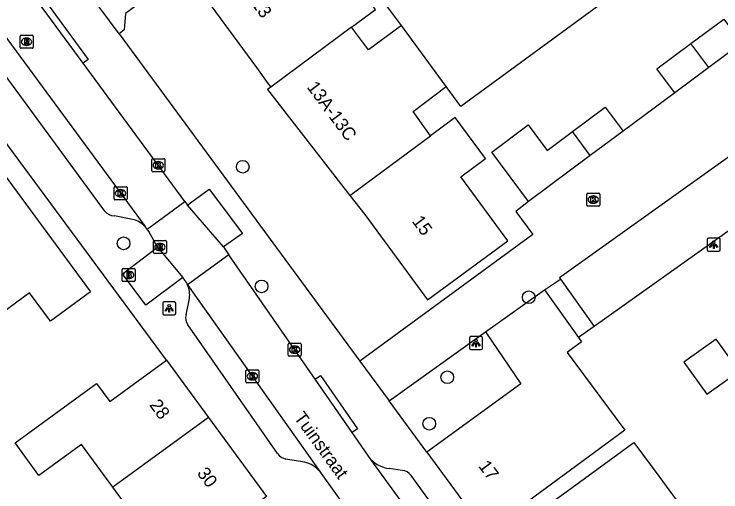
# Model space of a CAD drawing. Extents: x 161801 to 162379, y 382315 to 382832.
# Drawn here: x 161986.3 to 162040.7, y 382409.3 to 382446.1 of the extents above; entities that cross this region are included whole.
import ezdxf

# ---------------------------------------------------------------- set-up
doc = ezdxf.new("R2010")
doc.units = 0
for name, color, linetype in [('IMGEO_Boom', 7, 'Continuous'), ('IMGEO_Brandkraan', 7, 'Continuous'), ('IMGEO_Groenvoorziening', 7, 'Continuous'), ('IMGEO_Kolk', 7, 'Continuous'), ('IMGEO_Lichtpunt', 7, 'Continuous'), ('IMGEO_Openbare_ruimte_label', 7, 'Continuous'), ('IMGEO_Pand', 7, 'Continuous'), ('IMGEO_Pand_nummerreeks', 7, 'Continuous'), ('IMGEO_Parkeervlak_open', 7, 'Continuous'), ('IMGEO_Rijbaan_lokaal_open', 7, 'Continuous'), ('IMGEO_Rioolput', 7, 'Continuous'), ('IMGEO_Voetpad_open', 7, 'Continuous')]:
    doc.layers.add(name, color=color, linetype=linetype)

msp = doc.modelspace()

# ---------------------------------------------------------------- linework, layer by layer
at = {"layer": 'IMGEO_Boom'}
for centre in [(162003.926, 382434.351), (161994.753, 382428.459), (162005.374, 382425.139), (162025.931, 382424.312), (162019.656, 382418.146), (162018.277, 382414.57)]:
    msp.add_circle(centre, 0.489, dxfattribs=at)
at = {"layer": 'IMGEO_Brandkraan'}
for p, q in [((161994.641, 382425.6), (161994.641, 382426.452)), ((161994.716, 382426.526), (161995.568, 382426.526)), ((161995.129, 382426.306), (161995.154, 382426.306)), ((161995.642, 382426.452), (161995.642, 382425.6)), ((161995.152, 382425.746), (161995.127, 382425.746)), ((161995.568, 382425.526), (161994.716, 382425.526))]:
    msp.add_line(p, q, dxfattribs=at)
for points in [[(161994.641, 382425.6), (161994.641, 382426.452)], [(161994.716, 382426.526), (161995.568, 382426.526)], [(161994.989, 382426.226), (161994.989, 382425.826), (161995.202, 382425.826)], [(161995.22, 382426.226), (161994.989, 382426.226)], [(161995.168, 382426.145), (161995.114, 382426.145), (161995.114, 382426.069)], [(161995.642, 382426.452), (161995.642, 382425.6)], [(161995.114, 382426.069), (161995.167, 382426.069)], [(161995.176, 382425.993), (161995.114, 382425.993), (161995.114, 382425.912)], [(161995.114, 382425.912), (161995.176, 382425.912)], [(161995.568, 382425.526), (161994.716, 382425.526)]]:
    msp.add_lwpolyline(points, dxfattribs=at)
for centre, radius, start, end in [((161994.718, 382426.45), 0.0765, 91.552, 178.448), ((161994.718, 382426.45), 0.0765, 91.552, 178.448), ((161995.169, 382426.107), 0.0379, 267.8285, 90.9355), ((161995.224, 382426.081), 0.145, 59.4692, 91.5367), ((161995.249, 382426.128), 0.0922, 285.5137, 58.1501), ((161995.566, 382426.45), 0.0765, 1.552, 88.448), ((161995.566, 382426.45), 0.0765, 1.552, 88.448), ((161994.718, 382425.602), 0.0765, 181.552, 268.448), ((161994.718, 382425.602), 0.0765, 181.552, 268.448), ((161995.177, 382425.952), 0.0404, 269.8759, 90.5077), ((161995.208, 382426.077), 0.251, 268.6676, 293.5347), ((161995.254, 382425.936), 0.105, 301.3115, 78.989), ((161995.566, 382425.602), 0.0765, 271.552, 358.448), ((161995.566, 382425.602), 0.0765, 271.552, 358.448)]:
    msp.add_arc(centre, radius, start, end, dxfattribs=at)
for centre, major_axis, ratio, start_param, end_param in [((161995.128, 382426.026), (-0.387, 0.002), 0.722429, 4.712389, 7.853982), ((161995.153, 382426.026), (-0.39, 0.002), 0.717154, 1.570796, 4.712389)]:
    msp.add_ellipse(centre, major_axis=major_axis, ratio=ratio, start_param=start_param, end_param=end_param, dxfattribs=at)
at = {"layer": 'IMGEO_Groenvoorziening'}
msp.add_lwpolyline([(162030.961, 382422.046), (162029.76, 382421.198)], dxfattribs=at)
at = {"layer": 'IMGEO_Kolk'}
for p, q in [((161996.916, 382434.049), (161996.916, 382434.901)), ((161996.991, 382434.975), (161997.843, 382434.975)), ((161997.917, 382434.901), (161997.917, 382434.049)), ((161997.404, 382434.755), (161997.429, 382434.755)), ((161997.843, 382433.975), (161996.991, 382433.975)), ((161997.427, 382434.195), (161997.402, 382434.195)), ((161994.016, 382431.894), (161994.016, 382432.746)), ((161994.091, 382432.82), (161994.943, 382432.82)), ((161995.017, 382432.746), (161995.017, 382431.894)), ((161994.504, 382432.6), (161994.529, 382432.6)), ((162030.393, 382431.403), (162030.393, 382432.255)), ((162030.468, 382432.329), (162031.32, 382432.329)), ((162030.881, 382432.109), (162030.906, 382432.109)), ((162031.394, 382432.255), (162031.394, 382431.403)), ((161994.943, 382431.82), (161994.091, 382431.82)), ((161994.527, 382432.04), (161994.502, 382432.04)), ((162030.904, 382431.549), (162030.879, 382431.549)), ((162031.32, 382431.329), (162030.468, 382431.329)), ((162007.414, 382419.85), (162007.414, 382420.702)), ((162007.489, 382420.776), (162008.341, 382420.776)), ((162008.415, 382420.702), (162008.415, 382419.85)), ((162007.902, 382420.556), (162007.927, 382420.556)), ((162008.341, 382419.776), (162007.489, 382419.776)), ((162007.925, 382419.996), (162007.9, 382419.996)), ((162004.165, 382417.803), (162004.165, 382418.655)), ((162004.24, 382418.729), (162005.092, 382418.729)), ((162004.653, 382418.509), (162004.678, 382418.509)), ((162005.166, 382418.655), (162005.166, 382417.803)), ((162004.676, 382417.949), (162004.651, 382417.949)), ((162005.092, 382417.729), (162004.24, 382417.729))]:
    msp.add_line(p, q, dxfattribs=at)
for points in [[(161996.916, 382434.049), (161996.916, 382434.901)], [(161996.991, 382434.975), (161997.843, 382434.975)], [(161997.917, 382434.901), (161997.917, 382434.049)], [(161997.237, 382434.675), (161997.36, 382434.675), (161997.36, 382434.524), (161997.49, 382434.675), (161997.654, 382434.675), (161997.508, 382434.524), (161997.661, 382434.275), (161997.509, 382434.275), (161997.424, 382434.439), (161997.36, 382434.372), (161997.36, 382434.275), (161997.237, 382434.275), (161997.237, 382434.675)], [(161997.843, 382433.975), (161996.991, 382433.975)], [(161994.016, 382431.894), (161994.016, 382432.746)], [(161994.091, 382432.82), (161994.943, 382432.82)], [(161995.017, 382432.746), (161995.017, 382431.894)], [(161994.337, 382432.52), (161994.46, 382432.52), (161994.46, 382432.369), (161994.59, 382432.52), (161994.754, 382432.52), (161994.608, 382432.369), (161994.761, 382432.12), (161994.609, 382432.12), (161994.524, 382432.284), (161994.46, 382432.217), (161994.46, 382432.12), (161994.337, 382432.12), (161994.337, 382432.52)], [(162030.393, 382431.403), (162030.393, 382432.255)], [(162030.468, 382432.329), (162031.32, 382432.329)], [(162031.394, 382432.255), (162031.394, 382431.403)], [(161994.943, 382431.82), (161994.091, 382431.82)], [(162030.714, 382432.029), (162030.837, 382432.029), (162030.837, 382431.878), (162030.967, 382432.029), (162031.131, 382432.029), (162030.985, 382431.878), (162031.138, 382431.629), (162030.986, 382431.629), (162030.901, 382431.793), (162030.837, 382431.726), (162030.837, 382431.629), (162030.714, 382431.629), (162030.714, 382432.029)], [(162031.32, 382431.329), (162030.468, 382431.329)], [(162007.414, 382419.85), (162007.414, 382420.702)], [(162007.489, 382420.776), (162008.341, 382420.776)], [(162008.415, 382420.702), (162008.415, 382419.85)], [(162007.735, 382420.476), (162007.858, 382420.476), (162007.858, 382420.325), (162007.988, 382420.476), (162008.152, 382420.476), (162008.006, 382420.325), (162008.159, 382420.076), (162008.007, 382420.076), (162007.922, 382420.24), (162007.858, 382420.173), (162007.858, 382420.076), (162007.735, 382420.076), (162007.735, 382420.476)], [(162008.341, 382419.776), (162007.489, 382419.776)], [(162004.165, 382417.803), (162004.165, 382418.655)], [(162004.24, 382418.729), (162005.092, 382418.729)], [(162005.166, 382418.655), (162005.166, 382417.803)], [(162004.486, 382418.429), (162004.609, 382418.429), (162004.609, 382418.278), (162004.739, 382418.429), (162004.903, 382418.429), (162004.757, 382418.278), (162004.91, 382418.029), (162004.758, 382418.029), (162004.673, 382418.193), (162004.609, 382418.126), (162004.609, 382418.029), (162004.486, 382418.029), (162004.486, 382418.429)], [(162005.092, 382417.729), (162004.24, 382417.729)]]:
    msp.add_lwpolyline(points, dxfattribs=at)
for centre, start, end in [((161996.993, 382434.899), 91.552, 178.448), ((161996.993, 382434.899), 91.552, 178.448), ((161997.841, 382434.899), 1.552, 88.448), ((161997.841, 382434.899), 1.552, 88.448), ((161996.993, 382434.051), 181.552, 268.448), ((161996.993, 382434.051), 181.552, 268.448), ((161997.841, 382434.051), 271.552, 358.448), ((161997.841, 382434.051), 271.552, 358.448), ((161994.093, 382432.744), 91.552, 178.448), ((161994.093, 382432.744), 91.552, 178.448), ((161994.941, 382432.744), 1.552, 88.448), ((161994.941, 382432.744), 1.552, 88.448), ((162030.47, 382432.253), 91.552, 178.448), ((162030.47, 382432.253), 91.552, 178.448), ((162031.318, 382432.253), 1.552, 88.448), ((162031.318, 382432.253), 1.552, 88.448), ((161994.093, 382431.896), 181.552, 268.448), ((161994.093, 382431.896), 181.552, 268.448), ((161994.941, 382431.896), 271.552, 358.448), ((161994.941, 382431.896), 271.552, 358.448), ((162030.47, 382431.405), 181.552, 268.448), ((162030.47, 382431.405), 181.552, 268.448), ((162031.318, 382431.405), 271.552, 358.448), ((162031.318, 382431.405), 271.552, 358.448), ((162007.491, 382420.7), 91.552, 178.448), ((162007.491, 382420.7), 91.552, 178.448), ((162008.339, 382420.7), 1.552, 88.448), ((162008.339, 382420.7), 1.552, 88.448), ((162007.491, 382419.852), 181.552, 268.448), ((162007.491, 382419.852), 181.552, 268.448), ((162008.339, 382419.852), 271.552, 358.448), ((162008.339, 382419.852), 271.552, 358.448), ((162004.242, 382418.653), 91.552, 178.448), ((162004.242, 382418.653), 91.552, 178.448), ((162005.09, 382418.653), 1.552, 88.448), ((162005.09, 382418.653), 1.552, 88.448), ((162004.242, 382417.805), 181.552, 268.448), ((162004.242, 382417.805), 181.552, 268.448), ((162005.09, 382417.805), 271.552, 358.448), ((162005.09, 382417.805), 271.552, 358.448)]:
    msp.add_arc(centre, 0.0765, start, end, dxfattribs=at)
for centre, major_axis, ratio, start_param, end_param in [((161997.403, 382434.475), (-0.387, 0.002), 0.722429, 4.712389, 7.853982), ((161997.428, 382434.475), (-0.39, 0.002), 0.717154, 1.570796, 4.712389), ((161994.503, 382432.32), (-0.387, 0.002), 0.722429, 4.712389, 7.853982), ((161994.528, 382432.32), (-0.39, 0.002), 0.717154, 1.570796, 4.712389), ((162030.88, 382431.829), (-0.387, 0.002), 0.722429, 4.712389, 7.853982), ((162030.905, 382431.829), (-0.39, 0.002), 0.717154, 1.570796, 4.712389), ((162007.901, 382420.276), (-0.387, 0.002), 0.722429, 4.712389, 7.853982), ((162007.926, 382420.276), (-0.39, 0.002), 0.717154, 1.570796, 4.712389), ((162004.652, 382418.229), (-0.387, 0.002), 0.722429, 4.712389, 7.853982), ((162004.677, 382418.229), (-0.39, 0.002), 0.717154, 1.570796, 4.712389)]:
    msp.add_ellipse(centre, major_axis=major_axis, ratio=ratio, start_param=start_param, end_param=end_param, dxfattribs=at)
at = {"layer": 'IMGEO_Lichtpunt'}
for p, q in [((162040.565, 382428.853), (162039.757, 382428.853)), ((162040.565, 382428.853), (162039.757, 382428.853)), ((162039.663, 382428.758), (162039.663, 382427.951)), ((162039.663, 382428.758), (162039.663, 382427.951)), ((162040.659, 382427.951), (162040.659, 382428.758)), ((162040.659, 382427.951), (162040.659, 382428.758)), ((162039.757, 382427.857), (162040.565, 382427.857)), ((162039.757, 382427.857), (162040.565, 382427.857)), ((161998.666, 382423.96), (161997.858, 382423.96)), ((161998.666, 382423.96), (161997.858, 382423.96)), ((161997.764, 382423.865), (161997.764, 382423.058)), ((161997.764, 382423.865), (161997.764, 382423.058)), ((161998.76, 382423.058), (161998.76, 382423.865)), ((161998.76, 382423.058), (161998.76, 382423.865)), ((161997.858, 382422.964), (161998.666, 382422.964)), ((161997.858, 382422.964), (161998.666, 382422.964)), ((162022.272, 382421.276), (162021.464, 382421.276)), ((162022.272, 382421.276), (162021.464, 382421.276)), ((162021.37, 382421.181), (162021.37, 382420.374)), ((162021.37, 382421.181), (162021.37, 382420.374)), ((162022.366, 382420.374), (162022.366, 382421.181)), ((162022.366, 382420.374), (162022.366, 382421.181)), ((162021.464, 382420.28), (162022.272, 382420.28)), ((162021.464, 382420.28), (162022.272, 382420.28))]:
    msp.add_line(p, q, dxfattribs=at)
for points in [[(162040.037, 382428.422), (162040.076, 382428.394), (162039.888, 382428.132), (162039.85, 382428.159), (162040.037, 382428.422)], [(162040.139, 382428.374), (162040.186, 382428.374), (162040.186, 382428.052), (162040.139, 382428.052), (162040.139, 382428.374)], [(162040.249, 382428.394), (162040.287, 382428.421), (162040.474, 382428.159), (162040.435, 382428.131), (162040.249, 382428.394)], [(161998.138, 382423.529), (161998.177, 382423.501), (161997.989, 382423.239), (161997.951, 382423.266), (161998.138, 382423.529)], [(161998.24, 382423.481), (161998.287, 382423.481), (161998.287, 382423.159), (161998.24, 382423.159), (161998.24, 382423.481)], [(161998.35, 382423.501), (161998.388, 382423.528), (161998.575, 382423.266), (161998.536, 382423.238), (161998.35, 382423.501)], [(162021.744, 382420.845), (162021.783, 382420.817), (162021.595, 382420.555), (162021.557, 382420.582), (162021.744, 382420.845)], [(162021.846, 382420.797), (162021.893, 382420.797), (162021.893, 382420.475), (162021.846, 382420.475), (162021.846, 382420.797)], [(162021.956, 382420.817), (162021.994, 382420.844), (162022.181, 382420.582), (162022.142, 382420.554), (162021.956, 382420.817)]]:
    msp.add_lwpolyline(points, dxfattribs=at)
for centre in [(162040.162, 382428.556), (161998.263, 382423.663), (162021.869, 382420.979)]:
    msp.add_circle(centre, 0.0994, dxfattribs=at)
for centre, start, end in [((162039.757, 382428.758), 90, 180), ((162039.757, 382428.758), 90, 180), ((162040.565, 382428.758), 0, 90), ((162040.565, 382428.758), 0, 90), ((162039.757, 382427.951), 180, 270), ((162039.757, 382427.951), 180, 270), ((162040.565, 382427.951), 270, 0), ((162040.565, 382427.951), 270, 360), ((161997.858, 382423.865), 90, 180), ((161997.858, 382423.865), 90, 180), ((161998.666, 382423.865), 0, 90), ((161998.666, 382423.865), 0, 90), ((161997.858, 382423.058), 180, 270), ((161997.858, 382423.058), 180, 270), ((161998.666, 382423.058), 270, 0), ((161998.666, 382423.058), 270, 360), ((162021.464, 382421.181), 90, 180), ((162021.464, 382421.181), 90, 180), ((162022.272, 382421.181), 0, 90), ((162022.272, 382421.181), 0, 90), ((162021.464, 382420.374), 180, 270), ((162021.464, 382420.374), 180, 270), ((162022.272, 382420.374), 270, 0), ((162022.272, 382420.374), 270, 360)]:
    msp.add_arc(centre, 0.0946, start, end, dxfattribs=at)
at = {"layer": 'IMGEO_Pand'}
for points in [[(161958.958, 382469.924), (161992.199, 382424.732), (161989.125, 382422.47), (161987.511, 382424.66), (161983.375, 382421.618), (161982.644, 382421.08), (161983.026, 382420.561), (161982.715, 382420.332), (161982.033, 382421.259), (161971.982, 382434.924)], [(162016.135, 382445.239), (162015.069, 382446.675), (162028.864, 382456.929)], [(162012.297, 382445.1), (162014.128, 382446.461), (162011.818, 382449.569), (162009.909, 382448.237), (162006.221, 382453.297), (162000.03, 382448.734), (162004.978, 382441.988), (162005.81, 382440.854), (162006.084, 382440.48)], [(162039.058, 382452.455), (162020.713, 382438.983), (162019.568, 382440.542)], [(162038.414, 382443.841), (162040.929, 382445.711), (162042.301, 382443.865)], [(162016.135, 382445.239), (162013.597, 382443.352), (162012.297, 382445.1)], [(162019.568, 382440.542), (162016.135, 382445.239)], [(162012.297, 382445.1), (162006.084, 382440.48)], [(162037.165, 382440.047), (162035.793, 382441.893), (162038.414, 382443.841)], [(162039.786, 382441.995), (162038.414, 382443.841)], [(162042.301, 382443.865), (162039.786, 382441.995)], [(162039.786, 382441.995), (162037.165, 382440.047)], [(162006.084, 382440.48), (162005.83, 382440.291), (162012.164, 382432.155)], [(162018.358, 382436.738), (162017.04, 382438.599), (162019.568, 382440.542)], [(162029.29, 382437.06), (162031.82, 382438.94), (162033.192, 382437.094)], [(162012.164, 382432.155), (162013.313, 382430.679), (162015.736, 382427.395), (162018.139, 382424.104), (162024.326, 382428.653), (162020.709, 382433.572), (162022.593, 382434.996), (162020.263, 382438.147), (162018.358, 382436.738)], [(162025.905, 382431.677), (162023.078, 382435.482), (162025.888, 382437.57), (162027.343, 382435.613), (162029.29, 382437.06)], [(162030.663, 382435.214), (162029.29, 382437.06)], [(162033.192, 382437.094), (162030.663, 382435.214)], [(162012.164, 382432.155), (162018.358, 382436.738)], [(162030.663, 382435.214), (162025.905, 382431.677)], [(162022.598, 382421.64), (162027.154, 382424.872)], [(162027.154, 382424.872), (162029.76, 382421.198)], [(162022.598, 382421.64), (162025.311, 382417.648), (162018.079, 382412.392)], [(162029.76, 382421.198), (162029.989, 382420.875), (162028.892, 382420.064), (162033.311, 382414.087), (162022.628, 382406.187)], [(162037.863, 382419.316), (162039.637, 382416.846), (162042.114, 382418.625), (162040.34, 382421.095), (162037.863, 382419.316)], [(161993.912, 382409.693), (161991.524, 382412.972), (161988.238, 382410.58), (161986.401, 382413.104), (161992.675, 382417.668), (161993.681, 382416.287), (161998.059, 382419.476)], [(161998.059, 382419.476), (162001.282, 382415.062)], [(162001.282, 382415.062), (161993.912, 382409.693)], [(162001.282, 382415.062), (162005.738, 382408.96)], [(162023.288, 382405.3), (162034.023, 382413.125), (162035.94, 382410.533), (162037.275, 382408.724)], [(162018.079, 382412.392), (162022.628, 382406.187)], [(162005.738, 382408.96), (161993.858, 382400.416), (161991.849, 382403.174), (161996.3, 382406.414), (161993.912, 382409.693)]]:
    msp.add_lwpolyline(points, dxfattribs=at)
at = {"layer": 'IMGEO_Parkeervlak_open'}
for points in [[(162063.951, 382445.581), (162062.388, 382444.445), (162046.948, 382433.434), (162030.961, 382422.046)], [(162028.36, 382425.699), (162030.961, 382422.046)]]:
    msp.add_lwpolyline(points, dxfattribs=at)
at = {"layer": 'IMGEO_Rijbaan_lokaal_open'}
for points in [[(161966.539, 382470.379), (161996.412, 382429.744)], [(162005.757, 382454.164), (161994.889, 382446.161), (161994.794, 382444.891), (161994.413, 382444.586)], [(162063.951, 382445.581), (162061.27, 382449.381), (162044.277, 382437.229), (162028.301, 382425.803), (162028.36, 382425.699)], [(161994.413, 382444.586), (161991.438, 382448.62)], [(161991.637, 382442.328), (161988.124, 382447.103)], [(161999.468, 382431.685), (161991.637, 382442.328)], [(162037.165, 382440.047), (162033.192, 382437.094)], [(161996.57, 382429.553), (161999.468, 382431.685)], [(161999.468, 382431.685), (161999.673, 382431.407)], [(162025.905, 382431.677), (162024.941, 382430.922), (162026.252, 382429.136), (162012.934, 382419.392)], [(162002.433, 382428.179), (162000, 382431.025), (161999.673, 382431.407)], [(161996.57, 382429.553), (161996.412, 382429.744)], [(161997.372, 382428.158), (161996.682, 382429.377), (161996.57, 382429.553)], [(161997.372, 382428.158), (161999.316, 382425.829)], [(162002.433, 382428.179), (162002.849, 382427.58)], [(162002.849, 382427.58), (161999.682, 382425.259)], [(162009.488, 382418.005), (162002.849, 382427.58)], [(161999.682, 382425.259), (161999.609, 382425.413), (161999.316, 382425.829)], [(162027.154, 382424.872), (162028.36, 382425.699)], [(161999.682, 382425.259), (162009.841, 382410.886)], [(162015.189, 382416.324), (162022.598, 382421.64)], [(162012.934, 382419.392), (162015.189, 382416.324)], [(162012.33, 382413.906), (162009.488, 382418.005)], [(162013.778, 382411.818), (162012.33, 382413.906)], [(162032.83, 382385.614), (162013.778, 382411.818)], [(162009.841, 382410.886), (162009.951, 382410.728), (162018.719, 382398.49)]]:
    msp.add_lwpolyline(points, dxfattribs=at)
at = {"layer": 'IMGEO_Rioolput'}
for p, q in [((161986.787, 382443.548), (161986.787, 382444.4)), ((161986.862, 382444.474), (161987.714, 382444.474)), ((161987.275, 382444.254), (161987.3, 382444.254)), ((161987.788, 382444.4), (161987.788, 382443.548)), ((161987.298, 382443.694), (161987.273, 382443.694)), ((161987.714, 382443.474), (161986.862, 382443.474)), ((161997.047, 382427.75), (161997.047, 382428.602)), ((161997.122, 382428.676), (161997.974, 382428.676)), ((161997.535, 382428.456), (161997.56, 382428.456)), ((161998.048, 382428.602), (161998.048, 382427.75)), ((161997.558, 382427.896), (161997.533, 382427.896)), ((161997.974, 382427.676), (161997.122, 382427.676))]:
    msp.add_line(p, q, dxfattribs=at)
for points in [[(161986.787, 382443.548), (161986.787, 382444.4)], [(161986.862, 382444.474), (161987.714, 382444.474)], [(161987.376, 382444.172), (161987.124, 382444.174), (161987.124, 382443.774)], [(161987.302, 382444.093), (161987.248, 382444.093), (161987.248, 382444.012)], [(161987.788, 382444.4), (161987.788, 382443.548)], [(161987.124, 382443.774), (161987.248, 382443.774), (161987.248, 382443.936), (161987.259, 382443.936)], [(161987.248, 382444.012), (161987.3, 382444.012)], [(161987.306, 382443.907), (161987.377, 382443.774), (161987.517, 382443.774), (161987.452, 382443.9)], [(161987.714, 382443.474), (161986.862, 382443.474)], [(161997.047, 382427.75), (161997.047, 382428.602)], [(161997.122, 382428.676), (161997.974, 382428.676)], [(161997.636, 382428.374), (161997.384, 382428.376), (161997.384, 382427.976)], [(161997.562, 382428.295), (161997.508, 382428.295), (161997.508, 382428.214)], [(161998.048, 382428.602), (161998.048, 382427.75)], [(161997.384, 382427.976), (161997.508, 382427.976), (161997.508, 382428.138), (161997.519, 382428.138)], [(161997.508, 382428.214), (161997.56, 382428.214)], [(161997.566, 382428.109), (161997.637, 382427.976), (161997.777, 382427.976), (161997.712, 382428.102)], [(161997.974, 382427.676), (161997.122, 382427.676)]]:
    msp.add_lwpolyline(points, dxfattribs=at)
for centre, radius, start, end in [((161986.864, 382444.398), 0.0765, 91.552, 178.448), ((161986.864, 382444.398), 0.0765, 91.552, 178.448), ((161987.308, 382443.997), 0.0964, 77.0061, 93.1865), ((161987.322, 382444.054), 0.0378, 276.6634, 79.6772), ((161987.375, 382444.062), 0.109, 350.3612, 89.416), ((161987.373, 382444.062), 0.112, 277.5842, 350.9817), ((161987.712, 382444.398), 0.0765, 1.552, 88.448), ((161987.712, 382444.398), 0.0765, 1.552, 88.448), ((161986.864, 382443.55), 0.0765, 181.552, 268.448), ((161986.864, 382443.55), 0.0765, 181.552, 268.448), ((161987.258, 382443.883), 0.0533, 26.0293, 88.6989), ((161987.284, 382444.201), 0.19, 274.7715, 282.9687), ((161987.357, 382443.847), 0.108, 29.5134, 73.7905), ((161987.712, 382443.55), 0.0765, 271.552, 358.448), ((161987.712, 382443.55), 0.0765, 271.552, 358.448), ((161997.124, 382428.6), 0.0765, 91.552, 178.448), ((161997.124, 382428.6), 0.0765, 91.552, 178.448), ((161997.568, 382428.199), 0.0964, 77.0061, 93.1865), ((161997.582, 382428.256), 0.0378, 276.6634, 79.6772), ((161997.635, 382428.264), 0.109, 350.3612, 89.416), ((161997.972, 382428.6), 0.0765, 1.552, 88.448), ((161997.972, 382428.6), 0.0765, 1.552, 88.448), ((161997.124, 382427.752), 0.0765, 181.552, 268.448), ((161997.124, 382427.752), 0.0765, 181.552, 268.448), ((161997.518, 382428.085), 0.0533, 26.0293, 88.6989), ((161997.544, 382428.403), 0.19, 274.7715, 282.9687), ((161997.633, 382428.264), 0.112, 277.5842, 350.9817), ((161997.617, 382428.049), 0.108, 29.5134, 73.7905), ((161997.972, 382427.752), 0.0765, 271.552, 358.448), ((161997.972, 382427.752), 0.0765, 271.552, 358.448)]:
    msp.add_arc(centre, radius, start, end, dxfattribs=at)
for centre, major_axis, ratio, start_param, end_param in [((161987.274, 382443.974), (-0.387, 0.002), 0.722429, 4.712389, 7.853982), ((161987.299, 382443.974), (-0.39, 0.002), 0.717154, 1.570796, 4.712389), ((161997.534, 382428.176), (-0.387, 0.002), 0.722429, 4.712389, 7.853982), ((161997.559, 382428.176), (-0.39, 0.002), 0.717154, 1.570796, 4.712389)]:
    msp.add_ellipse(centre, major_axis=major_axis, ratio=ratio, start_param=start_param, end_param=end_param, dxfattribs=at)
at = {"layer": 'IMGEO_Voetpad_open'}
for points in [[(161998.059, 382419.476), (161983.404, 382439.272), (161954.726, 382478.543)], [(161993.315, 382430.945), (161966.551, 382467.446)], [(161988.124, 382447.103), (161988.526, 382447.399), (161992.039, 382442.624), (161991.637, 382442.328)], [(161994.413, 382444.586), (162012.934, 382419.392)], [(161999.673, 382431.407), (162000, 382431.645), (162001.35, 382432.629), (162003.905, 382429.219), (162002.433, 382428.179)], [(161995.442, 382430.301), (161994.041, 382430.567)], [(161999.316, 382425.829), (161996.451, 382423.692), (161994.671, 382426.124), (161997.372, 382428.158)], [(161999.564, 382422.953), (161999.822, 382424.223)], [(162006.595, 382412.288), (162000, 382421.742), (161999.691, 382422.185)], [(162009.488, 382418.005), (162009.898, 382418.289), (162012.74, 382414.19), (162012.33, 382413.906)], [(162018.079, 382412.392), (162015.189, 382416.324)], [(162008.683, 382411.604), (162007.238, 382411.855)], [(162016.191, 382410.975), (162015.201, 382411.13)], [(162033.065, 382388.261), (162027.294, 382396.215), (162016.872, 382410.591)]]:
    msp.add_lwpolyline(points, dxfattribs=at)
for centre, radius, start, end in [((161994.041, 382431.453), 0.886, 214.9851, 270.0064), ((161995.018, 382428.44), 1.908, 43.0939, 77.1749), ((161997.841, 382424.483), 1.998, 352.5306, 22.8615), ((162000.351, 382422.689), 0.831, 161.4483, 217.3311), ((162007.409, 382412.803), 0.963, 212.3219, 259.765), ((162008.286, 382409.67), 1.974, 38.0139, 78.3854), ((162015.432, 382413.423), 2.304, 224.1377, 264.2561), ((162016.11, 382410.036), 0.943, 36.091, 85.0737)]:
    msp.add_arc(centre, radius, start, end, dxfattribs=at)

# ---------------------------------------------------------------- texts
at = {"layer": 'IMGEO_Openbare_ruimte_label'}
msp.add_text('Tuinstraat', height=1, rotation=306.1368, dxfattribs=at).set_placement((162007.813, 382415.033))
at = {"layer": 'IMGEO_Pand_nummerreeks'}
for s, rotation, p in [('13', 306.3654, (162004.545, 382446.903)), ('13A-13C', 306.6233, (162008.813, 382440.482)), ('15', 306.6256, (162016.899, 382430.151)), ('28', 306.1656, (161996.7, 382416.01)), ('17', 306.4857, (162022.01, 382411.306)), ('30', 306.4309, (162000.36, 382410.759))]:
    msp.add_text(s, height=1, rotation=rotation, dxfattribs=at).set_placement(p)

doc.saveas('drawing.dxf')
